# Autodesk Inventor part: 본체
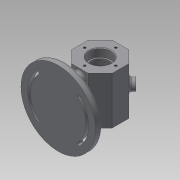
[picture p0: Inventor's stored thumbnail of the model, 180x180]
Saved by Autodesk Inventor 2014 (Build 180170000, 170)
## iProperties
Created: 2017-06
Part Number: 본체
Material: Generic
Document SubType Name: Modeling
Designer: user
Density: 1 g/cm^3
Appearance: Default
Author: user
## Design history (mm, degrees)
sketch "Sketch2"
  geometry: C1 r 55 at (0, 0); 1 further point
  constraints: 1 centre point, 1 coincident
extrude "Extrusion1" new body sketch "Sketch2" distance "d0" = 10; taper "d1" = 0 deg
sketch "Sketch3"
  geometry: L1 (-55, 0)-(-55, 10) reference; L2 (-55, 10)-(55, 10) reference; L3 (55, 10)-(55, 0) reference; L4 (55, 0)-(-55, 0) reference; L5 (0, 0)-(0, 62); L6 (12.426, 92)-(30, 74.426); L7 (30, 74.426)-(30, 49.574); L8 (30, 49.574)-(12.426, 32); L9 (12.426, 32)-(-12.426, 32); L10 (-12.426, 32)-(-30, 49.574); L11 (-30, 49.574)-(-30, 74.426); L12 (-30, 74.426)-(-12.426, 92); L13 (-12.426, 92)-(12.426, 92); 2 further points
  constraints: 18 end point, 1 midpoint, 17 other
extrude "Extrusion2" join sketch "Sketch3" stored distance "d2" = 70; taper "d3" = 0 deg
sketch "Sketch4"
  geometry: L1 (0, 55)-(10, 55) reference; L2 (10, 55)-(10, -55) reference; L3 (10, -55)-(0, -55) reference; L4 (0, -55)-(0, 55) reference; L5 (92, -35)-(32, -35) reference; L6 (32, -35)-(32, 35) reference; L7 (32, 35)-(92, 35) reference; L8 (92, 35)-(92, -35) reference; L9 (62, 35)-(62, -35); L10 (62, 35)-(78, 35); L11 (78, 35)-(78, 23.3); L12 (76, 23)-(76, 20); L13 (87, 17)-(87, -17); L14 (84, -20)-(76, -20); L15 (76, -20)-(76, -23); L16 (76, -23)-(77.7, -23); L17 (78, -23.3)-(78, -35); L18 (77.7, 23)-(76, 23); L19 (84, 20)-(76, 20); L20 (78, -35)-(62, -35); L21 (62, 35)-(62, -35); A1 r 0.3 centre (77.7, 23.3) between (77.7, 23) and (78, 23.3); A2 r 0.3 centre (77.7, -23.3) between (78, -23.3) and (77.7, -23); A3 r 3 centre (84, 17) between (87, 17) and (84, 20); A4 r 3 centre (84, -17) between (84, -20) and (87, -17); 1 further point
  constraints: 26 end point, 8 point on circle, 8 tangent, 4 centre point, 2 equal radius, 2 midpoint, 2 point on line
  dimensions: "d4" = 0.3 radius of A1; "d5" = 3 radius of A3
revolve "Revolution1" sketch "Sketch4" stored, may be unused: angle "d6" = 90 deg
sketch "Sketch6"
  geometry: L1 (0, 0)-(55, 0.071); L2 (0, 0)-(26.836, 26.905); L3 (33.898, 33.985)-(44.934, 45.049); L4 (26.905, -26.836)-(0, 0); L5 (0, 0)-(26.905, -26.836); L6 (33.985, -33.898)-(47.581, -47.459); L7 (47.581, -47.459)-(33.985, -33.898); L8 (-38.83, -38.952)-(-48.246, -48.396); L9 (0, 0)-(-26.828, -26.912); L10 (0, 0)-(-38, -0.059); L11 (0, 0)-(-26.912, 26.828); A1 r 55 centre (0, 0) between (55, 0.071) and (-38.83, -38.952) reference; A2 r 2 centre (-30.358, -30.453) between (-31.77, -31.869) and (-28.946, -29.037); A3 r 2 centre (-30.453, 30.358) between (-29.037, 28.946) and (-31.869, 31.77); A4 r 2 centre (30.445, -30.367) between (29.029, -28.954) and (31.861, -31.779); A5 r 2 centre (30.367, 30.445) between (31.779, 31.861) and (28.954, 29.029); A6 r 5 centre (30.367, 30.445) between (33.898, 33.985) and (26.836, 26.905); A7 r 41 centre (0, 0) between (29.029, -28.954) and (28.954, 29.029); A8 r 45 centre (0, 0) between (31.861, -31.779) and (31.779, 31.861); A9 r 5 centre (30.445, -30.367) between (26.905, -26.836) and (33.985, -33.898); A10 r 5 centre (-30.358, -30.453) between (-33.888, -33.994) and (-26.828, -26.912); A11 r 41 centre (0, 0) between (-29.037, 28.946) and (-28.946, -29.037); A12 r 45 centre (0, 0) between (-31.869, 31.77) and (-31.77, -31.869); A13 r 5 centre (-30.453, 30.358) between (-26.912, 26.828) and (-33.994, 33.888); A14 r 38 centre (0, 0) between (-26.912, 26.828) and (-26.828, -26.912); A15 r 38 centre (0, 0) between (26.905, -26.836) and (26.836, 26.905); A16 r 48 centre (0, 0) between (-33.994, 33.888) and (-33.888, -33.994); A17 r 48 centre (0, 0) between (33.985, -33.898) and (33.898, 33.985); 1 further point
  constraints: 35 point on circle, 22 end point, 16 centre point, 9 coincident, 2 other
extrude "Extrusion3" cut sketch "Sketch6" distance "d11" = 3; taper "d12" = 0 deg
sketch "Sketch7"
  geometry: C1 r 55 at (0, 0) reference; A1 r 41 centre (0, 0) between (-29.037, 28.946) and (-28.946, -29.037) reference; A2 r 2 centre (-30.358, -30.453) between (-31.77, -31.869) and (-28.946, -29.037) reference; A3 r 45 centre (0, 0) between (-31.869, 31.77) and (-31.77, -31.869) reference; A4 r 2 centre (-30.453, 30.358) between (-29.037, 28.946) and (-31.869, 31.77) reference; A5 r 5 centre (-30.453, 30.358) between (-26.912, 26.828) and (-33.994, 33.888) reference; A6 r 48 centre (0, 0) between (-33.994, 33.888) and (-33.888, -33.994) reference; A7 r 5 centre (-30.358, -30.453) between (-33.888, -33.994) and (-26.828, -26.912) reference; A8 r 38 centre (0, 0) between (-26.912, 26.828) and (-26.828, -26.912) reference; A9 r 41 centre (0, 0) between (29.029, -28.954) and (28.954, 29.029) reference; A10 r 2 centre (30.367, 30.445) between (31.779, 31.861) and (28.954, 29.029) reference; A11 r 45 centre (0, 0) between (31.861, -31.779) and (31.779, 31.861) reference; A12 r 2 centre (30.445, -30.367) between (29.029, -28.954) and (31.861, -31.779) reference; A13 r 5 centre (30.367, 30.445) between (33.898, 33.985) and (26.836, 26.905) reference; A14 r 38 centre (0, 0) between (26.905, -26.836) and (26.836, 26.905) reference; A15 r 5 centre (30.445, -30.367) between (26.905, -26.836) and (33.985, -33.898) reference; A16 r 48 centre (0, 0) between (33.985, -33.898) and (33.898, 33.985) reference; A17 r 2 centre (-30.358, -30.453) between (-31.77, -31.869) and (-28.946, -29.037); A18 r 2 centre (-30.453, 30.358) between (-29.037, 28.946) and (-31.869, 31.77); A19 r 2 centre (30.367, 30.445) between (31.779, 31.861) and (28.954, 29.029); A20 r 2 centre (30.445, -30.367) between (29.029, -28.954) and (31.861, -31.779); A21 r 45 centre (0, 0) between (31.861, -31.779) and (31.779, 31.861); A22 r 45 centre (0, 0) between (-31.869, 31.77) and (-31.77, -31.869); A23 r 41 centre (0, 0) between (29.029, -28.954) and (28.954, 29.029); A24 r 41 centre (0, 0) between (-29.037, 28.946) and (-28.946, -29.037)
  constraints: 16 point on circle, 8 centre point, 6 coincident
extrude "Extrusion4" cut sketch "Sketch7" stored distance "d13" = 3; taper "d14" = 0 deg
workplane "Work Plane1"
sketch "Sketch8"
  geometry: L1 (8.551, 10.352)-(8.551, 60.127); L2 (8.551, 60.127)-(15.756, 60.127); L3 (15.756, 60.127)-(15.756, 10.352); L4 (15.756, 10.352)-(8.551, 10.352); L5 (24.853, 0)-(0, 0) reference; 2 further points
  constraints: 1 point on line, 2 other
emboss "Emboss1" sketch "Sketch8" dims "d16" = 0.5, "d17" = 0
sketch "Sketch9"
  geometry: L1 (-5, -24)-(-5, 24); L2 (5, 24)-(5, -24); A1 r 5 centre (0, -24) between (-5, -24) and (5, -24); A2 r 5 centre (0, 24) between (5, 24) and (-5, 24)
  constraints: 4 end point, 4 point on circle, 2 centre point
extrude "Extrusion5" join sketch "Sketch9" stored distance "d18" = 3; taper "d19" = 0 deg
fillet "Fillet1" dims "d20" = 5
workplane "Work Plane2"
sketch "Sketch10"
  geometry: L1 (-24.853, 70)-(0, 70) reference; L2 (-12.426, 70)-(-12.426, 35); C1 r 8 at (-12.426, 35); 1 further point
  constraints: 2 end point, 1 centre point, 1 coincident, 1 midpoint
extrude "Extrusion6" join sketch "Sketch10" stored distance "d22" = 3; taper "d23" = 0 deg
sketch "Sketch11"
  geometry: C1 r 8 at (0, 0) reference; 2 further points
  constraints: 1 coincident
hole "Hole1" sketch "Sketch11" at (0, 0) diameter "d24" = 8; stored, may be unused: countersink angle "d28" = 90 deg, drill point angle "d30" = 118 deg; dims "d25" = 6, "d26" = 4, "d27" = 2, "d29" = 30
chamfer "Chamfer1" distance "d31" = 1; stored, may be unused: second distance "d32" = 2, angle "d33" = 45 deg
fillet "Fillet2" dims "d34" = 3
sketch "Sketch12"
  geometry: L1 (-32.438, 7)-(-28.279, 7) reference; L2 (-28.279, 7)-(-28.279, 10) reference; L3 (-28.279, 10)-(28.566, 10) reference; L4 (28.566, 10)-(28.566, 7) reference; L5 (28.566, 7)-(32.324, 7) reference; L6 (32.324, 7)-(32.324, 10) reference; L7 (32.324, 10)-(42.426, 10) reference; L8 (42.426, 10)-(42.426, 0) reference; L9 (42.426, 0)-(-42.426, 0) reference; L10 (-42.426, 0)-(-42.426, 10) reference; L11 (-42.426, 10)-(-32.438, 10) reference; L12 (-32.438, 10)-(-32.438, 7) reference; L13 (-12.426, 32)-(-30, 49.574) reference; L14 (-30, 49.574)-(-30, 74.426) reference; L15 (-30, 74.426)-(-12.426, 92) reference; L16 (-12.426, 92)-(12.426, 92) reference; L17 (12.426, 92)-(30, 74.426) reference; L18 (30, 74.426)-(30, 49.574) reference; L19 (30, 49.574)-(12.426, 32) reference; L20 (12.426, 32)-(-12.426, 32) reference; L21 (0, 85)-(0, 39); L22 (23, 62)-(-23, 62); C1 r 16 at (0, 62) reference; A1 r 23 centre (0, 62) between (0, 85) and (0, 39); 5 further points
  constraints: 5 coincident, 4 end point, 4 point on circle, 1 centre point
hole "Hole2" sketch "Sketch12" at (0, 85), (23, 62), (0, 39), (-23, 62) diameter "d35" = 3.459; stored, may be unused: countersink angle "d39" = 90 deg, drill point angle "d41" = 118 deg; dims "d36" = 8, "d37" = 4, "d38" = 2, "d40" = 10
sketch "Sketch13"
  geometry: L1 (0, 85)-(0, 39); L2 (23, 62)-(-23, 62); C1 r 16 at (0, 62) reference; A1 r 23 centre (0, 62) between (0, 85) and (0, 39); 5 further points
  constraints: 5 coincident, 4 end point, 4 point on circle, 1 centre point
hole "Hole3" sketch "Sketch13" at (-23, 62), (0, 39), (23, 62), (0, 85) diameter "d42" = 3.459; stored, may be unused: countersink angle "d46" = 90 deg, drill point angle "d48" = 118 deg; dims "d43" = 8, "d44" = 4, "d45" = 2, "d47" = 10
chamfer "Chamfer2" distance "d49" = 1; stored, may be unused: second distance "d50" = 2, angle "d51" = 45 deg
fillet "Fillet3" dims "d52" = 3
fillet "Fillet4" dims "d53" = 1
body "Solid1"
node "Project Cut Edges1"
node "Project Cut Edges2"
node "Project Cut Edges3"
node "Project Cut Edges4"
node "Project Cut Edges5"
node "Project Cut Edges6"
other parameters: "d7" = 45 deg, "d8" = 45 deg, "d9" = 45 deg, "d10" = 45 deg, "d21" = 7
